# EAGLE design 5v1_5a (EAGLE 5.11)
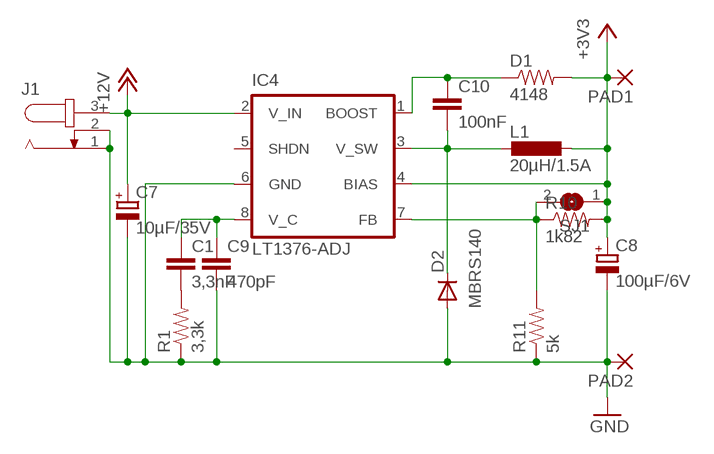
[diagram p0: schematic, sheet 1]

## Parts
C1  3,3nF  CAP0805  [0805]
C7  10µF/35V  CPOL-EUSMCD  [SMC_D]
C8  100µF/6V  CPOL-EUSMCD  [SMC_D]
C9  470pF  CAP0805  [0805]
C10  100nF  CAP0805  [0805]
D1  4148  RESISTOR1206  [1206]
D2  MBRS140  DIODE-SMB  [SMB]
IC4  LT1376-ADJ  LT1376  [SO-08]
J1  JACK-PLUG0  [SPC4077]
L1  20µH/1.5A  DO3316P  [DO3316P]
PAD1  SMD5  [SMD2,54-5,08]
PAD2  SMD5  [SMD2,54-5,08]
R1  3,3k  RESISTOR  [0805]
R10  1k82  RESISTOR  [0805]
R11  5k  RESISTOR  [0805]
SJ1  SJ  [SJ]

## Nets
+12V: C7.+ IC4.2(V_IN) J1.3
GND: C7.- C8.- C9.2 D2.A IC4.6(GND) J1.1 J1.2 PAD2.1(P) R1.1 R11.1
N$1: C1.2 R1.2
N$10: IC4.7(FB) R10.1 R11.2 SJ1.2
N$56: C1.1 C9.1 IC4.8(V_C)
N$57: C10.2 D2.C IC4.3(V_SW) L1.1
N$58: C10.1 D1.1 IC4.1(BOOST)
VCC: C8.+ D1.2 IC4.4(BIAS) L1.2 PAD1.1(P) R10.2 SJ1.1 ; supply symbol labelled +3V3
Unconnected: IC4.5(SHDN)

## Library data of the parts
C1 C9 C10 = SparkFun:CAP: Capacitor
C7 C8 = resistor:CPOL-EU: POLARIZED CAPACITOR, European symbol
D1 R1 R10 R11 = SparkFun:RESISTOR: Resistor
D2 = diode:DIODE-: DIODE
IC4 = v-reg:LT1376
J1 = con-jack:JACK-PLUG: DC POWER JACK Power Jack, DC, Right Angle, Through Hole, Rated 5A at 16VDC, PC Terminals Distributor: Farnell (www.Farnell.de) Drawing: 84N1161.pdf / 84N1162.pdf Manufacturer: SPC Technology (www.spctechnology.com) Type: SPC4077 / SPC 4078
L1 = inductor-coilcraft:DO3316P: COILCRAFT; OC_FARNELL: unknown; OC_NEWARK: unknown
PAD1 PAD2 = wirepad:SMD5: SMD PAD
SJ1 = jumper:SJ: SMD solder JUMPER

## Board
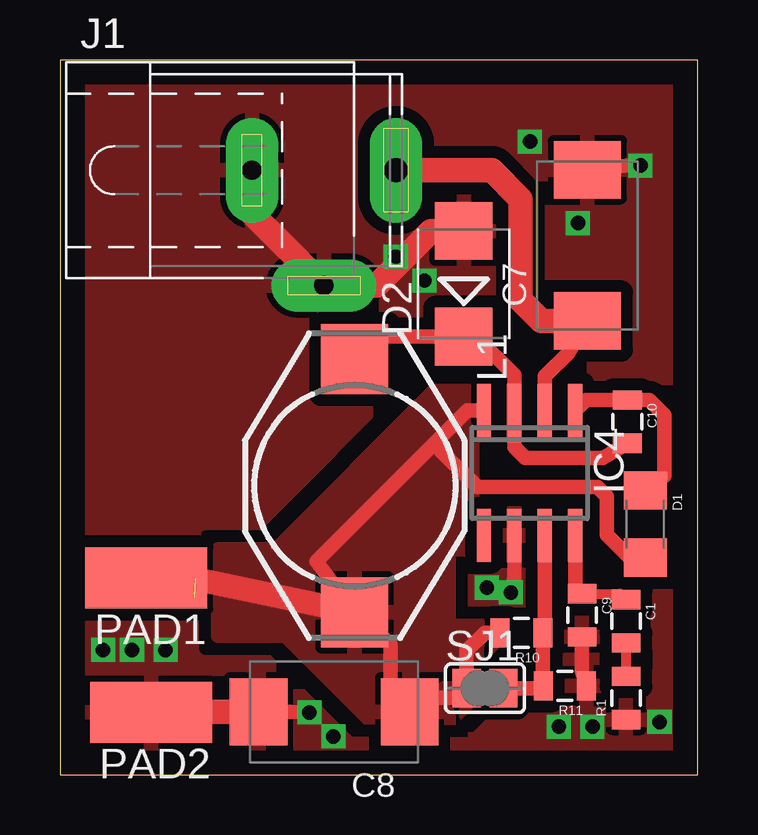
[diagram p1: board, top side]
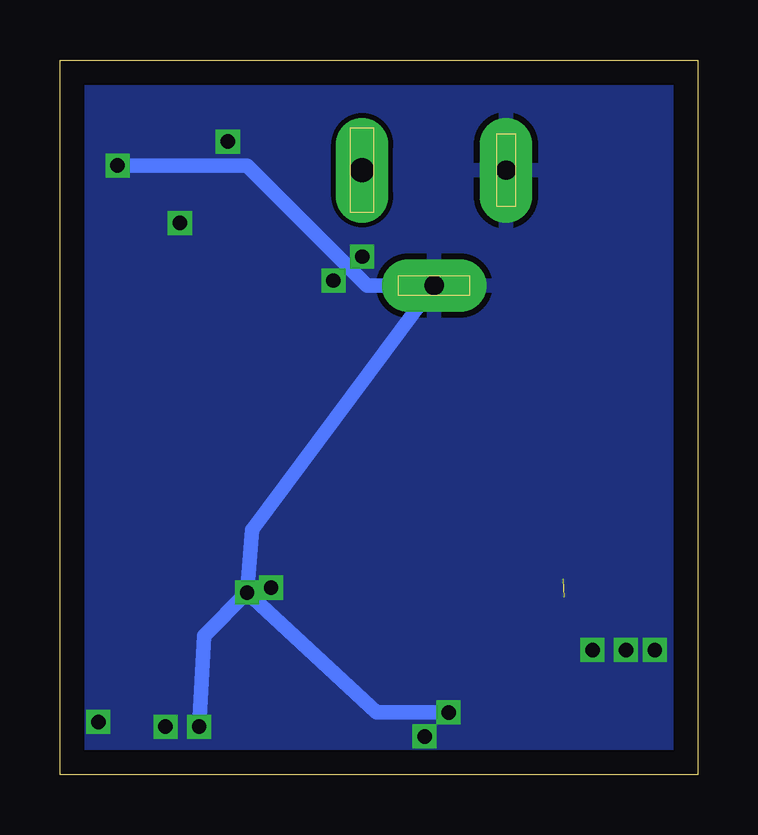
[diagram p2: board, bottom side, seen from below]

Size 26.6 x 29.8 mm. Coordinates in mm from the lower left corner, seen from the top.
Outline: 0,0 26.6,0 26.6,29.8 0,29.8 0,0
Copper layers (1*16): Top 0.035mm / dielectric 1.5mm / Bottom 0.035mm
Design rules "default *": minimum track width 10mil, minimum drill 24mil, track to track 8mil, track to pad 8mil, pad to pad 8mil, via to via 8mil, smd to smd 8mil, copper to edge 40mil, drill to drill 8mil, minimum pad ring 10mil, minimum via ring 8mil, stop-mask expansion 4mil, vias tented up to drill 24mil, thermal gap 10mil

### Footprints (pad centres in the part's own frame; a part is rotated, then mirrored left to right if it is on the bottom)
0805 = smd 0.8 x 1.2: 1 -0.9,0; 2 0.9,0
SMC_D = smd 2.4 x 2.8: + -3.15,0; - 3.15,0
1206 = smd 1.6 x 1.8: 1 -1.4,0; 2 1.4,0
SMB = smd 2.4 x 2.4: A 2.2,0; C -2.2,0
SO-08 = smd 0.6 x 2.2: 1 -1.905,-2.6; 2 -0.635,-2.6; 3 0.635,-2.6; 4 1.905,-2.6; 5 1.905,2.6; 6 0.635,2.6; 7 -0.635,2.6; 8 -1.905,2.6
SPC4077 = drill 0.8 pad 2.184 long: 1 -3,0; 2 0,-4.8 | drill 1 pad 2.184 long: 3 3,0
DO3316P = smd 2.92 x 2.79: 1 -5.28,0; 2 5.28,0
SMD2,54-5,08 = smd 2.54 x 5.08: 1 0,0
SJ = smd 1.168 x 1.6: 1 -0.762,0; 2 0.762,0

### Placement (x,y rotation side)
C1  23.6,6.4 270 top
C7  21.99,22.07 90 top
C8  11.43,2.62 180 top
C9  21.77,6.65 270 top
C10  23.66,14.72 270 top
D1  24.4,10.45 270 top
D2  16.84,20.47 90 top
IC4  19.58,12.58 180 top
J1  11,25.2 0 top
L1  12.29,12.05 270 top
PAD1  3.6,8.2 90 top
PAD2  3.8,2.6 90 top
R1  23.6,3.2 90 top
R10  19.24,5.91 180 top
R11  21.05,3.71 180 top
SJ1  17.72,3.61 0 top

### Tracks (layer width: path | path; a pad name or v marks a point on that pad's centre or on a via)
+12V
  Top 0.61: IC4.2 20.21,16.62 21.19,17.59 C7.+
  Top 1.016: J1.3 18,25.2 19.2,24 19.2,19.8 20.08,18.92 C7.+
GND  (via drill 0.6)
  Top 0.61: C9.2 21.77,4.29 R11.1 | IC4.6 18.95,8.14 v18.8,7.6 | C8.- 9.58,2.62 v10.4,2.6 | C7.- 23.78,25.42 v24.2,25.4
  Top 1.016: PAD2.1 3.02,2.62 C8.- | J1.1 8,23.4 J1.2 13.2,20.4 15.47,22.67 D2.A
  Bottom 0.61: v18.8,7.6 18.6,10.2 J1.2 13.8,20.4 18.8,25.4 v24.2,25.4 | v20.8,2 20.6,5.8 v18.8,7.6 | v10.4,2.6 13.4,2.6 v18.8,7.6
  other vias: 21.6,23 19.6,26.4 14,21.6 1.8,5.2 3,5.2 22.2,2 25,2.2 15.2,20.6 4.4,5.2 17.8,7.8 11.4,1.6
  pour Bottom: 0,29.8 26.6,29.8 26.6,0 0,0
  pour Top (isolate 0.5, rank 2): 0,0 26.6,0 26.6,29.8 0,29.8
N$1
  Top 0.406: C1.2 R1.2
N$10
  Top 0.61: IC4.7 20.21,6.19 R10.1 20.14,4.12 R11.2 20.05,3.61 SJ1.2
N$56
  Top 0.406: C9.1 23.35,7.55 C1.1
  Top 0.61: C9.1 21.48,7.77 IC4.8
N$57
  Top 0.61: L1.1 11.63,18.27 D2.C 17.33,18.27 18.95,16.66 IC4.3 18.95,13.65 19.4,13.2 22.64,13.2 C10.2
N$58
  Top 0.61: IC4.1 21.93,15.62 C10.1 24.58,15.62 25.2,15 25.2,12.45 D1.1
VCC  (1 unrouted)
  Top 0.61: 15.6,13.8 10.69,8.89 L1.2 12.43,6.77 13.78,5.42 13.78,3.2 | 15.6,13.8 16.98,15.18 IC4.4 | R10.2 17.71,5.91 16.96,5.16 SJ1.1 16.55,3.2 13.78,3.2 | 13.78,3.2 C8.+ | D1.2 23.75,9.05 22.8,10 22.8,11.6 22.4,12 17.4,12 15.6,13.8 | 5.8,9 5.6,9 5.6,7.4
  Top 1.016: PAD1.1 5.63,8.17 L1.2
  pour Top (isolate 0.5): 6.6,5.8 9.4,5.8 13.6,1.6 15.6,1.6 17,3 17,4.4 18.2,5.6 18.2,6.2 16.2,6.2 16.2,9.4 17.2,9.4 17.2,16 15.6,16 9,9.4 6.6,9.4

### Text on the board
tStop: +
bStop: + | -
